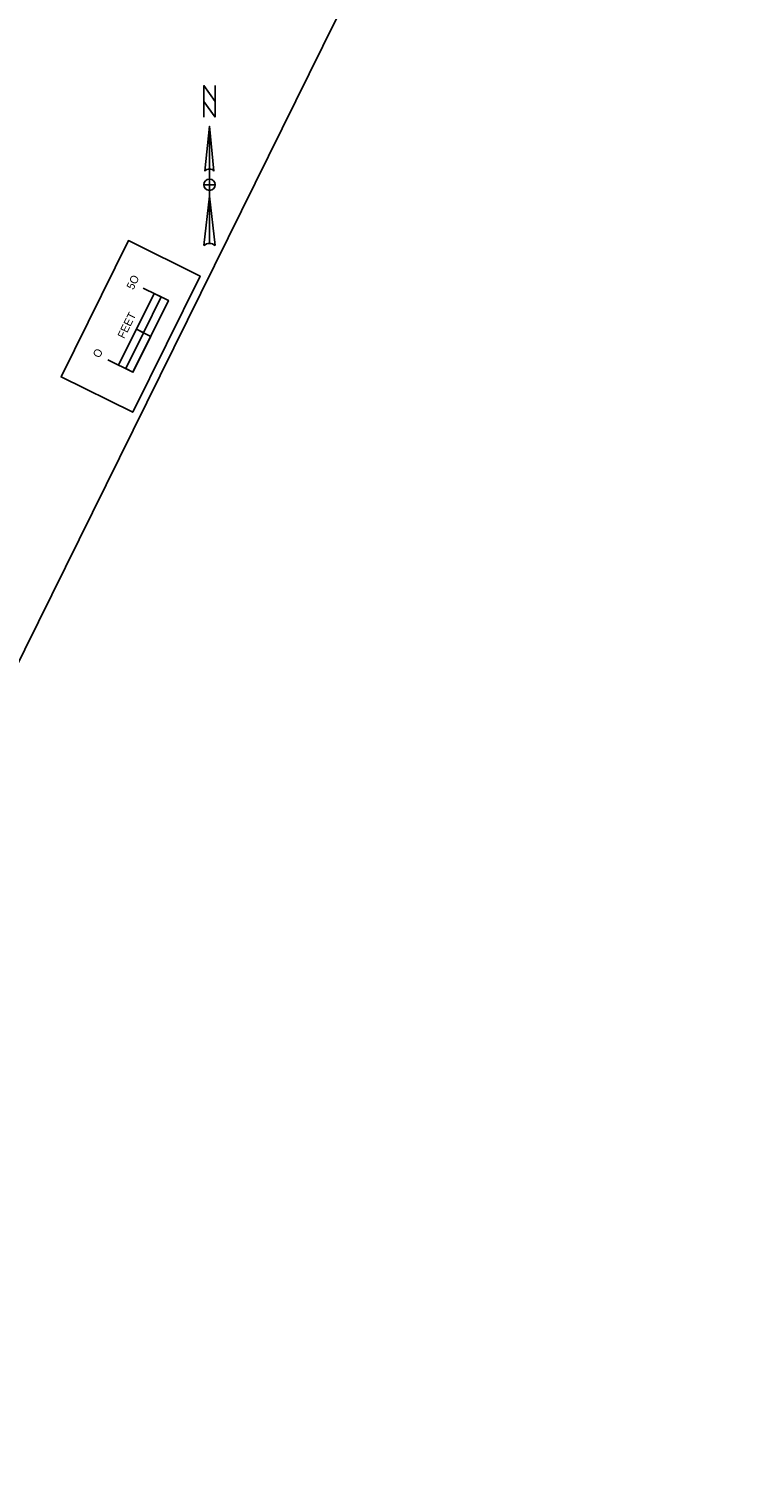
# Model space of a CAD drawing. Extents: x 14104283 to 14129344, y 8637090 to 8673339.
# Drawn here: x 14119794 to 14120232, y 8668497 to 8669399 of the extents above; entities that cross this region are included whole.
import ezdxf

# ---------------------------------------------------------------- set-up
doc = ezdxf.new("R2010")
doc.units = 0
for name, color, linetype in [('dsnCellsNorthArrow', 7, 'Continuous'), ('dsnCellsScaleBlock', 7, 'Continuous'), ('dsnNonPlotable', 7, 'Continuous')]:
    doc.layers.add(name, color=color, linetype=linetype)

msp = doc.modelspace()

# ---------------------------------------------------------------- linework, layer by layer
at = {"layer": 'dsnCellsNorthArrow'}
for p, q in [((14119906.81, 8669338.45), (14119909.63, 8669310.28)), ((14119906.81, 8669338.45), (14119906.81, 8669265.2)), ((14119904.11, 8669310.54), (14119904.63, 8669311.12)), ((14119904, 8669310.28), (14119904, 8669310.28)), ((14119903.29, 8669263.79), (14119906.81, 8669294.78)), ((14119906.81, 8669298.3), (14119906.81, 8669298.3))]:
    msp.add_line(p, q, dxfattribs=at)
msp.add_lwpolyline([(14119910.34, 8669344.08), (14119903.29, 8669353.94), (14119903.29, 8669363.8), (14119910.34, 8669353.94)], close=True, dxfattribs=at)
for points in [[(14119903.29, 8669344.08), (14119903.29, 8669363.8), (14119910.34, 8669353.94), (14119910.34, 8669363.8)], [(14119904, 8669310.28), (14119906.81, 8669338.45), (14119906.81, 8669311.68)], [(14119910.34, 8669301.82), (14119906.81, 8669301.82), (14119906.81, 8669305.35)], [(14119906.81, 8669298.3), (14119906.81, 8669301.82), (14119903.29, 8669301.82)], [(14119906.81, 8669265.2), (14119906.81, 8669294.78), (14119910.34, 8669263.79)]]:
    msp.add_lwpolyline(points, dxfattribs=at)
for centre, radius, start, end in [((14119906.81, 8669308.16), 3.52, 90.02039, 143.12574), ((14119906.81, 8669308.17), 3.52, 36.84806, 90.02184), ((14119906.81, 8669301.82), 3.52, 90, 180), ((14119906.81, 8669301.82), 3.52, 0, 90), ((14119906.81, 8669301.82), 3.52, 180, 270), ((14119906.81, 8669301.82), 3.52, 270, 360), ((14119906.81, 8669260.1), 5.1, 89.98939, 133.61895), ((14119906.81, 8669260.1), 5.11, 46.40206, 90.00064)]:
    msp.add_arc(centre, radius, start, end, dxfattribs=at)
at = {"layer": 'dsnCellsScaleBlock'}
msp.add_line((14119870.04, 8669207.12), (14119861.08, 8669211.55), dxfattribs=at)
msp.add_line((14119870.04, 8669207.12), (14119861.08, 8669211.55), dxfattribs=at)
for points in [[(14119814.03, 8669181.82), (14119856.13, 8669266.98), (14119900.95, 8669244.82), (14119858.85, 8669159.66)], [(14119858.85, 8669159.66), (14119814.03, 8669181.82), (14119856.13, 8669266.98), (14119900.95, 8669244.82)], [(14119865.53, 8669209.35), (14119876.61, 8669231.76), (14119872.16, 8669233.96), (14119861.08, 8669211.55)], [(14119858.96, 8669184.71), (14119870.04, 8669207.12), (14119865.53, 8669209.35), (14119854.45, 8669186.94)]]:
    msp.add_lwpolyline(points, close=True, dxfattribs=at)
for points in [[(14119843.27, 8669192.46), (14119858.96, 8669184.71), (14119881.12, 8669229.53), (14119865.43, 8669237.28)], [(14119850, 8669189.14), (14119872.16, 8669233.96)]]:
    msp.add_lwpolyline(points, dxfattribs=at)
at = {"layer": 'dsnNonPlotable'}
msp.add_lwpolyline([(14118631.64, 8668945.1), (14119326.37, 8670350.23), (14120231.75, 8669902.59), (14119537.02, 8668497.46)], close=True, dxfattribs=at)

# ---------------------------------------------------------------- texts
at = {"layer": 'dsnCellsScaleBlock'}
for s, p in [('5O', (14119859.14, 8669235.85)), ('FEET', (14119853.51, 8669205.28)), ('O', (14119838.07, 8669193.22))]:
    msp.add_text(s, height=5, rotation=63.69117, dxfattribs=at).set_placement(p)

doc.saveas('drawing.dxf')
